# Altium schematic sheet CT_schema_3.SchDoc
size 421 x 246 mm
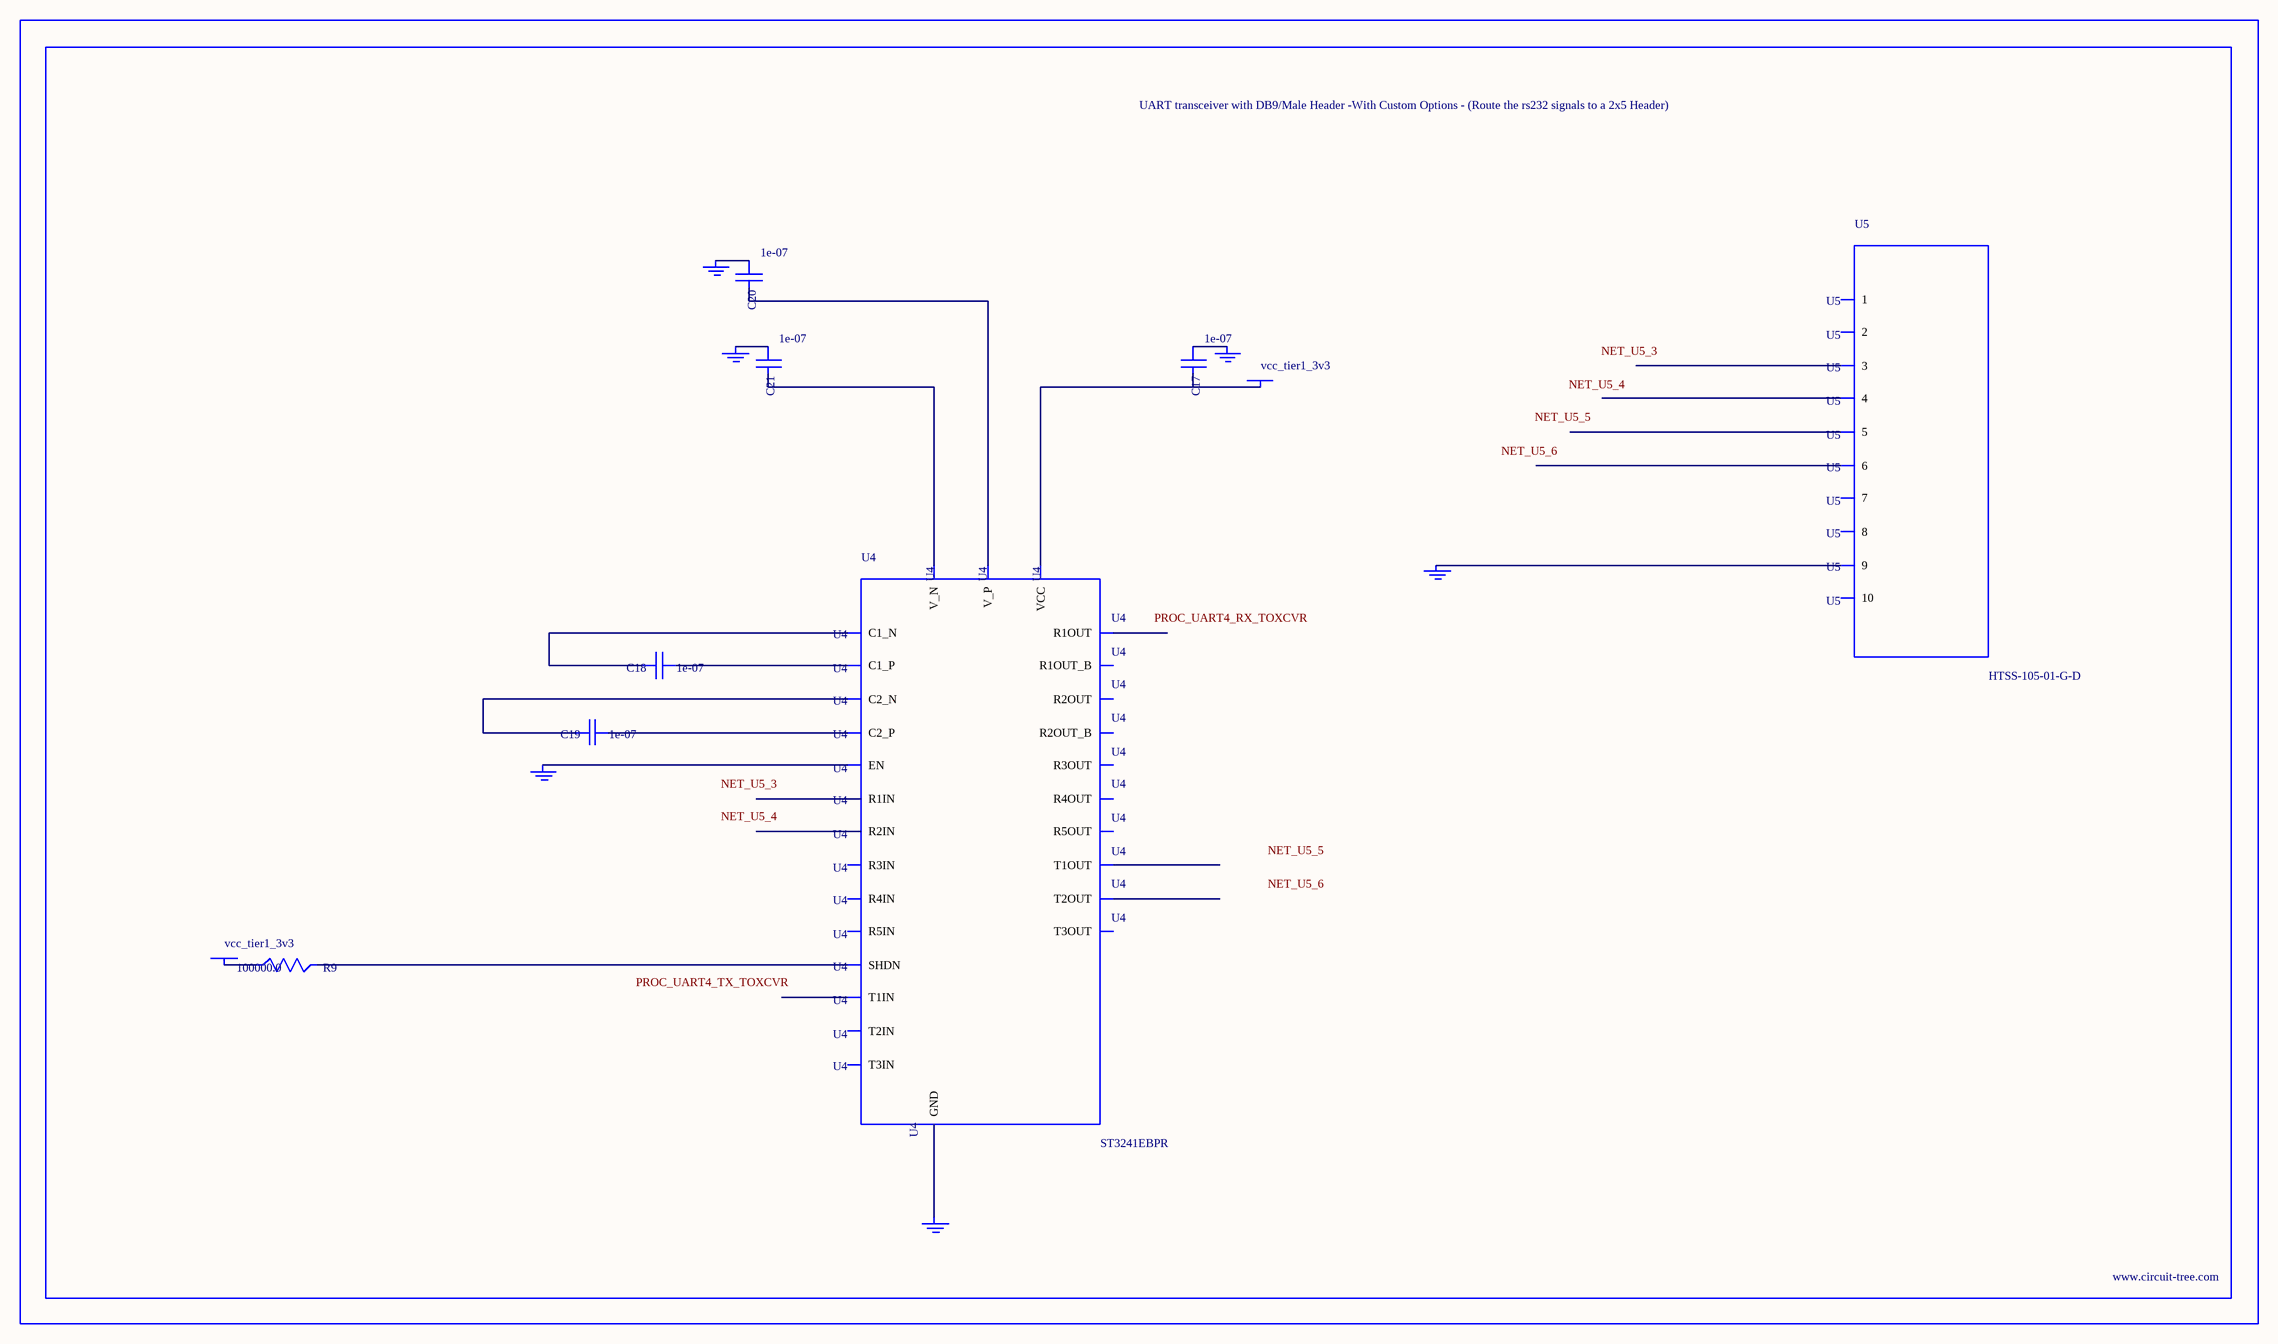
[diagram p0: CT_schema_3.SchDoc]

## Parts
BORDER2  (no value)
C17  1e-07  [C0402]
C18  1e-07  [C0402]
C19  1e-07  [C0402]
C20  1e-07  [C0402]
C21  1e-07  [C0402]
GND_INSTANCE_2_0  (no value)
GND_INSTANCE_2_1  (no value)
GND_INSTANCE_2_2  (no value)
GND_INSTANCE_2_3  (no value)
GND_INSTANCE_2_4  (no value)
GND_INSTANCE_2_5  (no value)
POWER_INSTANCE_2_0  vcc_tier1_3v3
POWER_INSTANCE_2_1  vcc_tier1_3v3
R9  100000.0  [R0603]
U4  ST3241EBPR  [SSOP-28]
U5  HTSS-105-01-G-D  [HTSS-105-01-G-D]

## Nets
NetC17_1: C17.1 GND_INSTANCE_2_2.0(GND)
NetC17_2: C17.2 POWER_INSTANCE_2_1.0(PWR) U4.26(VCC)
NetC18_1: C18.1 U4.28(C1_P)
NetC18_2: C18.2 U4.24(C1_N)
NetC19_1: C19.1 U4.1(C2_P)
NetC19_2: C19.2 U4.2(C2_N)
NetC20_1: C20.1 GND_INSTANCE_2_3.0(GND)
NetC20_2: C20.2 U4.27(V_P)
NetC21_1: C21.1 GND_INSTANCE_2_0.0(GND)
NetC21_2: C21.2 U4.3(V_N)
NetGND_INSTANCE_2_1_0: GND_INSTANCE_2_1.0(GND) U4.23(EN)
NetGND_INSTANCE_2_4_0: GND_INSTANCE_2_4.0(GND) U4.25(GND)
NetGND_INSTANCE_2_5_0: GND_INSTANCE_2_5.0(GND) U5.9
NetPOWER_INSTANCE_2_0_0: POWER_INSTANCE_2_0.0(PWR) R9.1
NetR9_2: R9.2 U4.22(SHDN)

Not connected (* = marked no-connect by the designer): U4 4(R1IN) 5(R2IN) 6(R3IN) 7(R4IN) 8(R5IN) 9(T1OUT) 10(T2OUT) 11(T3OUT) 12(T3IN) 13(T2IN) 14(T1IN) 15(R5OUT) 16(R4OUT) 17(R3OUT) 18(R2OUT) 19(R1OUT) 20(R2OUT_B) 21(R1OUT_B); U5 1 2 3 4 5 6 7 8 10

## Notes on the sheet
- Labels drawn without touching a wire or pin: NET_U5_3, NET_U5_4, NET_U5_5, NET_U5_6, PROC_UART4_RX_TOXCVR, PROC_UART4_TX_TOXCVR

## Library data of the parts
BORDER2 = BORDER_PAGE2
C17-C21 = C0402C104K3RACTU
GND_INSTANCE_2_0-GND_INSTANCE_2_5 = GND
POWER_INSTANCE_2_0 POWER_INSTANCE_2_1 = PWR
R9 = RC0603JR-07100KL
